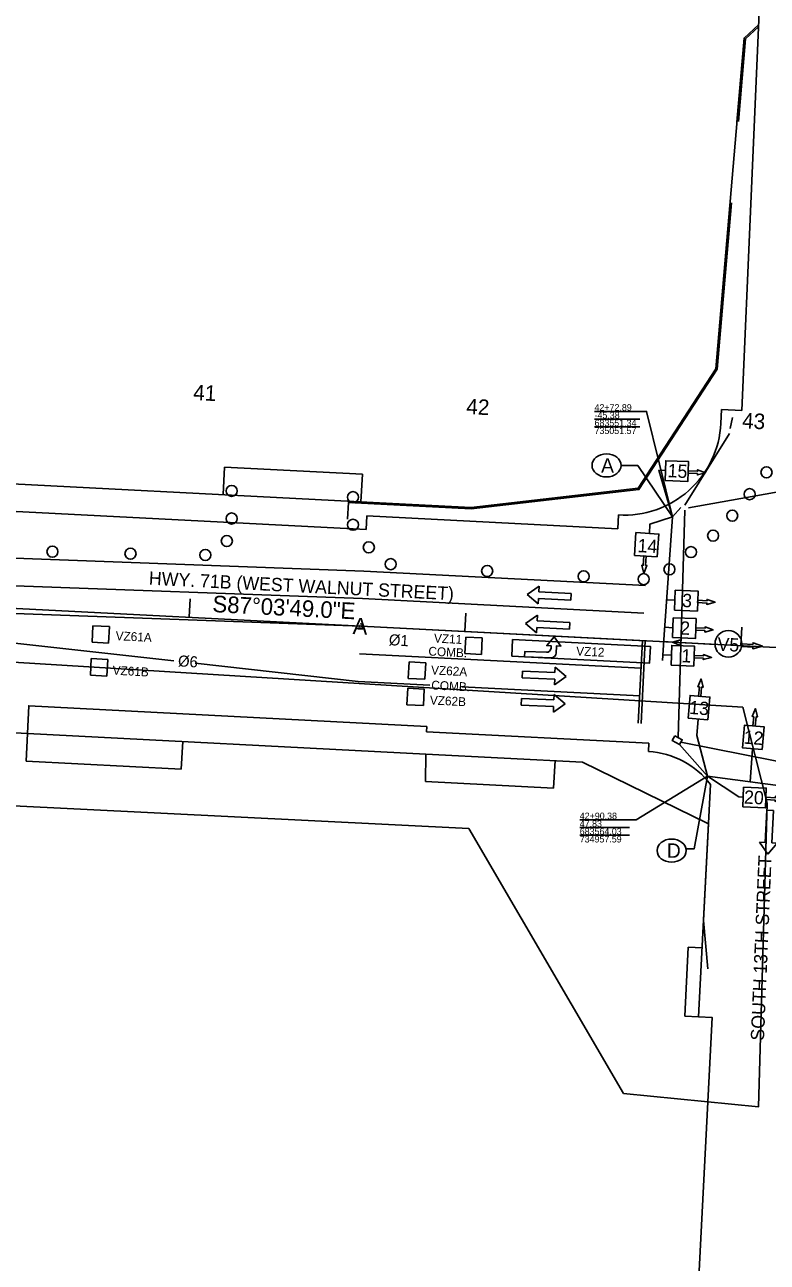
# Model space of a CAD drawing. Extents: x 679444 to 687671, y 733868 to 736107.
# Drawn here: x 683316.8 to 683585.7, y 734781.6 to 735229.7 of the extents above; entities that cross this region are included whole.
import ezdxf

# ---------------------------------------------------------------- set-up
doc = ezdxf.new("R2010")
doc.units = 0
for name, color, linetype in [('$', 7, 'Continuous'), ('090338 Base_ROW 3 - R_Horz Alg', 7, 'Continuous'), ('Clipping Boundary', 7, 'Continuous'), ('MOT Stage 1', 7, 'Continuous'), ('MOT Stage 1 Lanes', 7, 'Continuous'), ('R_Horz Alg', 7, 'Continuous'), ('R_Horz Alg Annot', 7, 'Continuous'), ('R_Horz Alg Station', 7, 'Continuous'), ('R_No_Plot', 7, 'Continuous'), ('R_TYPE_A_CURB', 7, 'Continuous'), ('RW-EX', 7, 'Continuous'), ('RW-PR', 7, 'Continuous'), ('SIGNAL-EX', 7, 'Continuous'), ('SIGNAL-PLAN VIEW LABLES', 7, 'Continuous'), ('TITEXT', 7, 'Continuous'), ('Video-Zones-pr', 7, 'Continuous')]:
    doc.layers.add(name, color=color, linetype=linetype)

# ---------------------------------------------------------------- blocks, each defined once
blk = doc.blocks.new('BAREL_1610')
at = {"layer": 'MOT Stage 1'}
blk.add_circle((0, 0.01), 2.88, dxfattribs=at)
blk = doc.blocks.new('BAREL_1611')
at = {"layer": 'MOT Stage 1'}
blk.add_circle((0, 0.01), 2.88, dxfattribs=at)
blk = doc.blocks.new('BAREL_1612')
at = {"layer": 'MOT Stage 1'}
blk.add_circle((0, 0.01), 2.88, dxfattribs=at)
blk = doc.blocks.new('BAREL_1613')
at = {"layer": 'MOT Stage 1'}
blk.add_circle((0, 0.01), 2.88, dxfattribs=at)
blk = doc.blocks.new('BAREL_1614')
at = {"layer": 'MOT Stage 1'}
blk.add_circle((0, 0.01), 2.88, dxfattribs=at)
blk = doc.blocks.new('SARROW_195')
at = {"layer": 'MOT Stage 1'}
for p, q in [((0, 0), (-6, 0)), ((0, -29.4), (0, 0)), ((-6, -29.4), (-6, 0)), ((-6, -29.4), (-11, -29.4)), ((-3, -39.8), (-11, -29.4)), ((5, -29.4), (-3, -39.8)), ((5, -29.4), (0, -29.4))]:
    blk.add_line(p, q, dxfattribs=at)
blk = doc.blocks.new('SARROW_196')
at = {"layer": 'MOT Stage 1'}
for p, q in [((0, 0), (-6, 0)), ((0, -29.4), (0, 0)), ((-6, -29.4), (-6, 0)), ((-6, -29.4), (-11, -29.4)), ((-3, -39.8), (-11, -29.4)), ((5, -29.4), (-3, -39.8)), ((5, -29.4), (0, -29.4))]:
    blk.add_line(p, q, dxfattribs=at)
blk = doc.blocks.new('SARROW_197')
at = {"layer": 'MOT Stage 1'}
for p, q in [((-6, -29.4), (-6, 0)), ((0, 0), (-6, 0)), ((0, -29.4), (0, 0)), ((-6, -29.4), (-11, -29.4)), ((-3, -39.8), (-11, -29.4)), ((5, -29.4), (-3, -39.8)), ((5, -29.4), (0, -29.4))]:
    blk.add_line(p, q, dxfattribs=at)
blk = doc.blocks.new('SARROW_198')
at = {"layer": 'MOT Stage 1'}
for p, q in [((-6, -29.4), (-6, 0)), ((0, 0), (-6, 0)), ((0, -29.4), (0, 0)), ((-6, -29.4), (-11, -29.4)), ((-3, -39.8), (-11, -29.4)), ((5, -29.4), (-3, -39.8)), ((5, -29.4), (0, -29.4))]:
    blk.add_line(p, q, dxfattribs=at)
blk = doc.blocks.new('BAREL_1673')
at = {"layer": 'MOT Stage 1'}
blk.add_circle((0, 0.01), 2.88, dxfattribs=at)
blk = doc.blocks.new('BAREL_1674')
at = {"layer": 'MOT Stage 1'}
blk.add_circle((0, 0.01), 2.88, dxfattribs=at)
blk = doc.blocks.new('BAREL_1675')
at = {"layer": 'MOT Stage 1'}
blk.add_circle((0, 0.01), 2.88, dxfattribs=at)
blk = doc.blocks.new('BAREL_1676')
at = {"layer": 'MOT Stage 1'}
blk.add_circle((0, 0.01), 2.88, dxfattribs=at)
blk = doc.blocks.new('BAREL_1677')
at = {"layer": 'MOT Stage 1'}
blk.add_circle((0, 0.01), 2.88, dxfattribs=at)
blk = doc.blocks.new('BAREL_1678')
at = {"layer": 'MOT Stage 1'}
blk.add_circle((0, 0.01), 2.88, dxfattribs=at)
blk = doc.blocks.new('BAREL_1679')
at = {"layer": 'MOT Stage 1'}
blk.add_circle((0, 0.01), 2.88, dxfattribs=at)
blk = doc.blocks.new('BAREL_1680')
at = {"layer": 'MOT Stage 1'}
blk.add_circle((0, 0.01), 2.88, dxfattribs=at)
blk = doc.blocks.new('SARROW_203')
at = {"layer": 'MOT Stage 1'}
for p, q in [((-6, -29.4), (-6, 0)), ((0, 0), (-6, 0)), ((0, -29.4), (0, 0)), ((-6, -29.4), (-11, -29.4)), ((-3, -39.8), (-11, -29.4)), ((5, -29.4), (-3, -39.8)), ((5, -29.4), (0, -29.4))]:
    blk.add_line(p, q, dxfattribs=at)
blk = doc.blocks.new('BAREL_1708')
at = {"layer": 'MOT Stage 1'}
blk.add_circle((0, 0.01), 2.88, dxfattribs=at)
blk = doc.blocks.new('BAREL_1709')
at = {"layer": 'MOT Stage 1'}
blk.add_circle((0, 0.01), 2.88, dxfattribs=at)
blk = doc.blocks.new('BAREL_1710')
at = {"layer": 'MOT Stage 1'}
blk.add_circle((0, 0.01), 2.88, dxfattribs=at)
blk = doc.blocks.new('BAREL_1711')
at = {"layer": 'MOT Stage 1'}
blk.add_circle((0, 0.01), 2.88, dxfattribs=at)
blk = doc.blocks.new('BAREL_1712')
at = {"layer": 'MOT Stage 1'}
blk.add_circle((0, 0.01), 2.88, dxfattribs=at)
blk = doc.blocks.new('BAREL_1713')
at = {"layer": 'MOT Stage 1'}
blk.add_circle((0, 0.01), 2.88, dxfattribs=at)

msp = doc.modelspace()

# ---------------------------------------------------------------- linework, layer by layer
at = {"layer": '$'}
msp.add_line((683547.74, 734999.56), (683548.38, 735008.82), dxfattribs=at)
at = {"layer": 'Clipping Boundary'}
msp.add_lwpolyline([(682208.27, 735067.14), (683202.96, 735005.68), (683576.79, 734982.58), (683585.61, 734947.81), (683582.55, 734837.97), (683533.65, 734842.79), (683477.58, 734938.67), (682209.6, 735001.84)], close=True, dxfattribs=at)
at = {"layer": 'MOT Stage 1'}
for points in [[(683509.26, 735002.33), (683509.25, 735002.01), (683509.35, 735004.76), (683510.95, 735004.7), (683508.51, 735008.11), (683505.83, 735004.89), (683507.43, 735004.83), (683507.4, 735004)], [(683505.74, 735002.46), (683497.89, 735002.75), (683497.82, 735000.83)], [(683497.82, 735000.83), (683507.59, 735000.47), (683507.27, 735000.48)]]:
    msp.add_lwpolyline(points, dxfattribs=at)
for centre, radius in [((683505.8, 735004.06), 1.6), ((683507.34, 735002.4), 1.92)]:
    msp.add_arc(centre, radius, 267.8614, 357.8614, dxfattribs=at)
at = {"layer": 'MOT Stage 1 Lanes'}
for p, q in [((683304.73, 735036.86), (683439.64, 735031.89)), ((683439.64, 735031.89), (683541.55, 735026.66)), ((683304.21, 735026.87), (683439.13, 735021.9)), ((683439.13, 735021.9), (683541.04, 735016.68)), ((683303.69, 735016.89), (683438.61, 735011.92)), ((683438.61, 735011.92), (683541.52, 735006.64)), ((683303.18, 735006.9), (683370.78, 734999.38)), ((683538.99, 734976.8), (683540.52, 735006.69)), ((683539.99, 734976.73), (683541.52, 735006.64)), ((683438.1, 735001.93), (683540.01, 734996.7)), ((683378.56, 734998.51), (683437.59, 734991.94)), ((683437.59, 734991.94), (683463.54, 734990.61)), ((683475.12, 734990.02), (683539.5, 734986.71))]:
    msp.add_line(p, q, dxfattribs=at)
at = {"layer": 'R_Horz Alg Annot'}
for p, q in [((683523.15, 735089.7), (683539.59, 735089.7)), ((683523.15, 735086.9), (683539.59, 735086.9)), ((683523.15, 735084.1), (683539.59, 735084.1)), ((683517.8, 734941.82), (683535.83, 734941.82)), ((683517.8, 734939.02), (683535.83, 734939.02)), ((683517.8, 734936.22), (683535.83, 734936.22))]:
    msp.add_line(p, q, dxfattribs=at)
for points in [[(683551.34, 735051.57), (683541.99, 735089.7), (683539.59, 735089.7)], [(683564.03, 734957.59), (683538.23, 734941.82), (683535.83, 734941.82)]]:
    msp.add_lwpolyline(points, dxfattribs=at)
at = {"layer": 'R_Horz Alg Station'}
for p, q in [((682930.35, 735038.18), (683438.62, 735011.92)), ((683438.62, 735011.92), (683602.68, 735003.5))]:
    msp.add_line(p, q, dxfattribs=at)
for points in [[(683376.69, 735021.79), (683376.35, 735015.13)], [(683476.56, 735016.64), (683476.22, 735009.99)], [(683576.43, 735011.52), (683576.09, 735004.86)]]:
    msp.add_lwpolyline(points, dxfattribs=at)
at = {"layer": 'R_No_Plot'}
msp.add_line((683554.42, 735054.91), (683551.34, 735051.57), dxfattribs=at)
at = {"layer": 'R_TYPE_A_CURB'}
for p, q in [((683577.31, 735224.82), (683582.52, 735229.59)), ((683577.79, 735224.58), (683582.49, 735228.89)), ((683574.71, 735194.45), (683577.31, 735224.82))]:
    msp.add_line(p, q, dxfattribs=at)
for points in [[(683575.24, 735194.67), (683577.79, 735224.58)], [(683433.76, 735050.72), (683434.07, 735056.71), (683478.54, 735054.43), (683539.25, 735061.37), (683567.57, 735104.98), (683572.72, 735165.22)], [(683564.16, 734940.5), (683564.4, 734940.38), (683562.6, 734905.43), (683564.2, 734887.82)]]:
    msp.add_lwpolyline(points, dxfattribs=at)
at = {"layer": 'RW-EX'}
for p, q in [((683579.69, 735164.78), (683593.35, 735477.74)), ((683576.43, 735089.96), (683579.69, 735164.78)), ((683568.91, 735085.34), (683569.17, 735090.33)), ((683569.17, 735090.33), (683576.43, 735089.96)), ((682951.92, 735072.12), (683440.41, 735046.87)), ((683440.41, 735046.87), (683440.66, 735051.86)), ((683440.66, 735051.86), (683531.55, 735047.2)), ((683531.55, 735047.2), (683531.8, 735052.19)), ((683436.82, 734976.96), (683462.39, 734975.65)), ((683462.39, 734975.65), (683462.29, 734973.65)), ((683462.29, 734973.65), (683542.86, 734969.52)), ((683542.86, 734969.52), (683542.71, 734966.52))]:
    msp.add_line(p, q, dxfattribs=at)
for points in [[(682968.24, 735001.18), (682967.74, 734991.19), (683067.68, 734986.03), (683317.82, 734973.1), (683318.3, 734983.09), (683436.82, 734976.96)], [(683565.13, 734954.62), (683560.81, 734870.47), (683565.8, 734870.21), (683545.76, 734479.81)]]:
    msp.add_lwpolyline(points, dxfattribs=at)
for centre, radius, start, end in [((683533.96, 735087.13), 35, 266.468, 357.0668), ((683541.17, 734936.56), 30, 37.0154, 87.0636)]:
    msp.add_arc(centre, radius, start, end, dxfattribs=at)
at = {"layer": 'RW-PR'}
for p, q in [((683389.17, 735069.54), (683388.66, 735059.56)), ((683389.17, 735069.54), (683439.11, 735066.96)), ((683439.11, 735066.96), (683438.59, 735056.98)), ((683317.82, 734973.1), (683317.34, 734963.11)), ((683373.51, 734960.21), (683374.03, 734970.19)), ((683461.97, 734955.65), (683462.1, 734965.65)), ((683317.34, 734963.11), (683373.51, 734960.21)), ((683508.87, 734963.25), (683508.35, 734953.27)), ((683461.97, 734955.65), (683508.35, 734953.27)), ((683555.81, 734870.72), (683557.1, 734895.7)), ((683557.1, 734895.7), (683562.09, 734895.44)), ((683560.81, 734870.47), (683555.81, 734870.72))]:
    msp.add_line(p, q, dxfattribs=at)
for points in [[(683582.52, 735229.59), (683577.31, 735224.82), (683567.08, 735105.15), (683538.96, 735061.84)], [(682953.3, 735102.08), (682980.75, 735110.68), (682985.75, 735110.42), (682989.19, 735080.2), (683277.18, 735065.32), (683449.96, 735056.39), (683478.52, 735054.93), (683538.96, 735061.84)], [(683317.82, 734973.1), (683462.1, 734965.65), (683518.85, 734962.74)], [(683518.85, 734962.74), (683564.4, 734940.38)]]:
    msp.add_lwpolyline(points, dxfattribs=at)
at = {"layer": 'SIGNAL-EX'}
for p, q in [((683572.25, 735083.54), (683573.1, 735087.51)), ((683555.79, 735055.72), (683571.97, 735081.74)), ((683551.34, 735051.57), (683548.38, 735008.82)), ((683564.03, 734957.59), (683601.5, 734952.7))]:
    msp.add_line(p, q, dxfattribs=at)
for points in [[(683633.68, 735068.46), (683557.16, 735054.83)], [(683553.48, 734971.62), (683555.79, 735053.94)], [(683553.94, 734969.07), (683564.03, 734957.59)], [(683554.4, 734969.91), (683634.28, 734954.17)]]:
    msp.add_lwpolyline(points, dxfattribs=at)
msp.add_lwpolyline([(683552.26, 734972.26), (683554.89, 734970.83), (683553.94, 734969.07), (683551.3, 734970.5)], close=True, dxfattribs=at)
at = {"layer": 'SIGNAL-PLAN VIEW LABLES'}
for points in [[(683548.71, 735064.67), (683548.96, 735071.8), (683557.21, 735071.52), (683556.96, 735064.32)], [(683545.88, 735037.05), (683537.66, 735037.54), (683538.15, 735045.79), (683546.44, 735045.29)], [(683552.13, 735017.78), (683552.38, 735024.91), (683560.64, 735024.62), (683560.39, 735017.42)], [(683551.42, 735007.8), (683551.67, 735014.93), (683559.93, 735014.65), (683559.68, 735007.45)], [(683550.85, 734997.82), (683551.1, 735004.95), (683559.35, 735004.66), (683559.1, 734997.46)], [(683551.34, 735006.17), (683554.36, 735007.04), (683554.22, 735004.96)], [(683564.18, 734978.02), (683557.07, 734978.63), (683557.77, 734986.86), (683564.95, 734986.24)], [(683583.86, 734967.24), (683576.75, 734967.85), (683577.45, 734976.08), (683584.63, 734975.47)], [(683576.85, 734946.47), (683577.09, 734953.6), (683585.35, 734953.32), (683585.1, 734946.12)]]:
    msp.add_lwpolyline(points, close=True, dxfattribs=at)
for points in [[(683532.78, 735070.07), (683538.78, 735070.07), (683551.34, 735051.57)], [(683551.34, 735051.57), (683546.48, 735068.37), (683548.83, 735068.24)], [(683560.42, 735067.18), (683560.39, 735066.68), (683563.38, 735067.45), (683560.49, 735068.53), (683560.46, 735068.02), (683557.1, 735068.19), (683557.06, 735067.36), (683560.42, 735067.18)], [(683557.06, 735067.36), (683560.42, 735067.18), (683560.39, 735066.68), (683563.38, 735067.45), (683560.49, 735068.53), (683560.46, 735068.02), (683557.1, 735068.19)], [(683551.34, 735051.57), (683543.2, 735048.87), (683543.03, 735045.5)], [(683540.79, 735033.98), (683540.29, 735034.01), (683541.06, 735031.01), (683542.13, 735033.91), (683541.63, 735033.94), (683541.8, 735037.29), (683540.96, 735037.34), (683540.79, 735033.98)], [(683540.96, 735037.34), (683540.79, 735033.98), (683540.29, 735034.01), (683541.06, 735031.01), (683542.13, 735033.91), (683541.63, 735033.94), (683541.8, 735037.29)], [(683549.26, 735021.51), (683552.26, 735021.34)], [(683563.84, 735020.29), (683563.81, 735019.79), (683566.81, 735020.56), (683563.91, 735021.63), (683563.88, 735021.13), (683560.53, 735021.3), (683560.48, 735020.46), (683563.84, 735020.29)], [(683560.48, 735020.46), (683563.84, 735020.29), (683563.81, 735019.79), (683566.81, 735020.56), (683563.91, 735021.63), (683563.88, 735021.13), (683560.53, 735021.3)], [(683548.55, 735011.54), (683551.55, 735011.37)], [(683563.13, 735010.31), (683563.1, 735009.81), (683566.1, 735010.58), (683563.2, 735011.66), (683563.17, 735011.15), (683559.82, 735011.33), (683559.77, 735010.49), (683563.13, 735010.31)], [(683559.77, 735010.49), (683563.13, 735010.31), (683563.1, 735009.81), (683566.1, 735010.58), (683563.2, 735011.66), (683563.17, 735011.15), (683559.82, 735011.33)], [(683548.3, 735006.34), (683551.34, 735006.17)], [(683554.29, 735006), (683566.79, 735005.3)], [(683580.46, 735004.34), (683580.43, 735003.74), (683584.02, 735004.66), (683580.55, 735005.95), (683580.51, 735005.35), (683576.49, 735005.56), (683576.44, 735004.55), (683580.46, 735004.34)], [(683576.44, 735004.55), (683580.46, 735004.34), (683580.43, 735003.74), (683584.02, 735004.66), (683580.55, 735005.95), (683580.51, 735005.35), (683576.49, 735005.56)], [(683547.98, 735001.55), (683550.97, 735001.38)], [(683562.55, 735000.33), (683562.52, 734999.83), (683565.52, 735000.6), (683562.62, 735001.67), (683562.59, 735001.17), (683559.24, 735001.34), (683559.19, 735000.5), (683562.55, 735000.33)], [(683559.19, 735000.5), (683562.55, 735000.33), (683562.52, 734999.83), (683565.52, 735000.6), (683562.62, 735001.67), (683562.59, 735001.17), (683559.24, 735001.34)], [(683561.94, 734989.87), (683562.44, 734989.84), (683561.75, 734992.85), (683560.6, 734989.98), (683561.1, 734989.94), (683560.84, 734986.59), (683561.68, 734986.52), (683561.94, 734989.87)], [(683561.68, 734986.52), (683561.94, 734989.87), (683562.44, 734989.84), (683561.75, 734992.85), (683560.6, 734989.98), (683561.1, 734989.94), (683560.84, 734986.59)], [(683581.62, 734979.1), (683582.12, 734979.06), (683581.43, 734982.07), (683580.28, 734979.2), (683580.78, 734979.16), (683580.52, 734975.81), (683581.36, 734975.75), (683581.62, 734979.1)], [(683581.36, 734975.75), (683581.62, 734979.1), (683582.12, 734979.06), (683581.43, 734982.07), (683580.28, 734979.2), (683580.78, 734979.16), (683580.52, 734975.81)], [(683564.03, 734957.59), (683560.21, 734972.32), (683560.62, 734978.32)], [(683579.47, 734955.58), (683580.3, 734967.55)], [(683564.03, 734957.59), (683559.2, 734931.31), (683556.26, 734931.31)], [(683564.03, 734957.59), (683575.37, 734950.13), (683576.97, 734950.04)], [(683588.55, 734948.98), (683588.53, 734948.48), (683591.52, 734949.25), (683588.62, 734950.33), (683588.6, 734949.82), (683585.24, 734950), (683585.2, 734949.16), (683588.55, 734948.98)], [(683585.2, 734949.16), (683588.55, 734948.98), (683588.53, 734948.48), (683591.52, 734949.25), (683588.62, 734950.33), (683588.6, 734949.82), (683585.24, 734950)], [(683545.85, 734931.31), (683545.78, 734931.31)]]:
    msp.add_lwpolyline(points, dxfattribs=at)
msp.add_circle((683571.63, 735005.53), 4.85, dxfattribs=at)
for centre in [(683527.51, 735070.13), (683551.06, 734930.68)]:
    msp.add_ellipse(centre, major_axis=(-5.27, 0), ratio=0.790685, dxfattribs=at)
at = {"layer": 'Video-Zones-pr'}
for points in [[(683341.54, 735012.08), (683341.23, 735006.09)], [(683347.53, 735011.77), (683341.54, 735012.08)], [(683347.53, 735011.77), (683347.22, 735005.78)], [(683347.22, 735005.78), (683341.23, 735006.09)], [(683476.5, 735007.97), (683476.2, 735001.98)], [(683482.5, 735007.66), (683476.5, 735007.97)], [(683482.5, 735007.66), (683482.19, 735001.67)], [(683340.93, 735000.18), (683340.62, 734994.18)], [(683346.92, 734999.87), (683340.93, 735000.18)], [(683346.92, 734999.87), (683346.61, 734993.87)], [(683482.19, 735001.67), (683476.2, 735001.98)], [(683456.02, 734999.01), (683455.71, 734993.02)], [(683462.01, 734998.7), (683456.02, 734999.01)], [(683462.01, 734998.7), (683461.7, 734992.71)], [(683346.61, 734993.87), (683340.62, 734994.18)], [(683461.7, 734992.71), (683455.71, 734993.02)], [(683455.53, 734989.48), (683455.22, 734983.49)], [(683461.52, 734989.17), (683455.53, 734989.48)], [(683461.52, 734989.17), (683461.21, 734983.18)], [(683461.21, 734983.18), (683455.22, 734983.49)]]:
    msp.add_lwpolyline(points, dxfattribs=at)
msp.add_lwpolyline([(683493.18, 735001.11), (683543.11, 734998.55), (683543.42, 735004.54), (683493.48, 735007.1)], close=True, dxfattribs=at)

# ---------------------------------------------------------------- block references
at = {"layer": 'MOT Stage 1'}
for name, p, xscale, yscale, rotation in [('BAREL_1713', (683585.42, 735067.62), 0.6945420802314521, 0.6945420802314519, 87.04179557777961), ('BAREL_1610', (683391.74, 735060.9), 0.6945420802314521, 0.6945420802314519, 87.04179557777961), ('BAREL_1611', (683435.68, 735058.63), 0.6945420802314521, 0.6945420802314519, 87.04179557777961), ('BAREL_1712', (683579.31, 735059.71), 0.6945420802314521, 0.6945420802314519, 87.04179557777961), ('BAREL_1711', (683573.02, 735051.94), 0.6945420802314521, 0.6945420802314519, 87.04179557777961), ('BAREL_1612', (683391.74, 735050.9), 0.6945420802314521, 0.6945420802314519, 87.04179557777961), ('BAREL_1614', (683435.68, 735048.63), 0.6945420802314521, 0.6945420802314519, 87.04179557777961), ('BAREL_1613', (683390.02, 735042.75), 0.6945420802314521, 0.6945420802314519, 87.04179557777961), ('BAREL_1710', (683566.09, 735044.72), 0.6945420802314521, 0.6945420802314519, 87.04179557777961), ('BAREL_1673', (683326.89, 735038.91), 0.6945420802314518, 0.6945420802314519, 116.71114235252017), ('BAREL_1674', (683355.14, 735038.17), 0.6945420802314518, 0.6945420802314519, 116.71114235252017), ('BAREL_1675', (683382.26, 735037.71), 0.6945420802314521, 0.6945420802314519, 87.04179557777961), ('BAREL_1676', (683441.43, 735040.45), 0.6945420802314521, 0.6945420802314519, 87.04179557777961), ('BAREL_1709', (683558.08, 735038.74), 0.6945420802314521, 0.6945420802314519, 87.04179557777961), ('BAREL_1677', (683449.37, 735034.37), 0.6945420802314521, 0.6945420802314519, 87.04179557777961), ('BAREL_1678', (683484.29, 735031.91), 0.6945420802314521, 0.6945420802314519, 87.04179557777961), ('BAREL_1679', (683519.23, 735029.97), 0.6945420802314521, 0.6945420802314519, 87.04179557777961), ('BAREL_1680', (683540.93, 735028.94), 0.6945420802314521, 0.6945420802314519, 87.04179557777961), ('BAREL_1708', (683550.28, 735032.48), 0.6945420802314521, 0.6945420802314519, 87.04179557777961), ('SARROW_198', (683514.61, 735021.38), 0.39999999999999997, 0.4, -92.95654264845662), ('SARROW_197', (683514.03, 735010.87), 0.39999999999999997, 0.4, -92.95654264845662), ('SARROW_195', (683496.97, 734993.2), 0.40000000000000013, -0.4000000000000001, -92.4271609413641), ('SARROW_196', (683496.59, 734983.31), 0.40000000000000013, -0.4000000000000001, -92.4271609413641), ('SARROW_203', (683587.98, 734945.23), 0.4, 0.39999999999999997, -3.300150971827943)]:
    msp.add_blockref(name, p, dxfattribs=dict(at, xscale=xscale, yscale=yscale, rotation=rotation))

# ---------------------------------------------------------------- texts
at = {"layer": '$'}
for s, height, rotation, p in [('41', 5.6, 357.0415, (683377.75, 735093.83)), ('42', 5.6, 357.0415, (683476.63, 735088.74)), ('43', 5.6, 357.0415, (683576.49, 735083.61)), ('HWY. 71B (WEST WALNUT STREET)', 4.8, 357.0637, (683361.7, 735026.97)), ('VZ61A', 3.2, 357.0415, (683349.69, 735006.89)), ('VZ11', 3.2, 357.0415, (683464.94, 735006.01)), ('COMB.', 3.2, 357.0415, (683462.93, 735001.31)), (' VZ12', 3.2, 357.0415, (683515.25, 735001.43)), ('VZ61B', 3.2, 357.0415, (683348.59, 734994.39)), ('VZ62A', 3.2, 357.0415, (683463.9, 734994.48)), ('COMB.', 3.2, 357.0415, (683463.98, 734989.03)), ('VZ62B', 3.2, 357.0415, (683463.46, 734983.6)), ('SOUTH 13TH STREET', 4.8, 87.5995, (683584.49, 734861.81))]:
    msp.add_text(s, height=height, rotation=rotation, dxfattribs=at).set_placement(p)
at = {"layer": '090338 Base_ROW 3 - R_Horz Alg'}
msp.add_text('A', height=2.4, rotation=357.0526, dxfattribs=at).set_placement((683437.36, 735010.78))
at = {"layer": 'R_Horz Alg'}
msp.add_text('A', height=6, rotation=357.0526, dxfattribs=at).set_placement((683435.47, 735009.07))
at = {"layer": 'R_Horz Alg Annot'}
for s, p in [('42+72.89', (683523.15, 735089.9)), ('-45.38', (683523.15, 735087.1)), ('683551.34', (683523.15, 735084.3)), ('735051.57', (683523.15, 735081.5)), ('42+90.38', (683517.8, 734942.02)), ('47.83', (683517.8, 734939.22)), ('683564.03', (683517.8, 734936.42)), ('734957.59', (683517.8, 734933.62))]:
    msp.add_text(s, height=2.4, dxfattribs=at).set_placement(p)
at = {"layer": 'R_Horz Alg Station'}
msp.add_text('S87%%d03\'49.0"E', height=6, rotation=357.0636, dxfattribs=at).set_placement((683384.69, 735017.05))
at = {"layer": 'SIGNAL-PLAN VIEW LABLES'}
for s, p in [('A', (683525.53, 735067.53)), ('D', (683549.33, 734928.08))]:
    msp.add_text(s, height=5.2, dxfattribs=at).set_placement(p)
for s, rotation, p in [('15', 357.0414, (683549.51, 735065.9)), ('14', 357.0414, (683538.63, 735038.74)), ('3', 357.0414, (683554.76, 735018.91)), ('2', 357.0414, (683554.05, 735008.93)), ('V5', 357.0414, (683567.56, 735003.08)), ('1', 357.0414, (683554.51, 734998.9)), ('13', 355.5482, (683557.31, 734980.2)), ('12', 355.5482, (683576.99, 734969.42)), ('20', 357.0414, (683577.19, 734947.72))]:
    msp.add_text(s, height=4.8, rotation=rotation, dxfattribs=at).set_placement(p)
at = {"layer": 'TITEXT'}
for s, p in [('%%C1', (683448.6, 735005.09)), ('%%C6', (683372.25, 734997.41))]:
    msp.add_text(s, height=4, rotation=356.2723, dxfattribs=at).set_placement(p)

doc.saveas('drawing.dxf')
